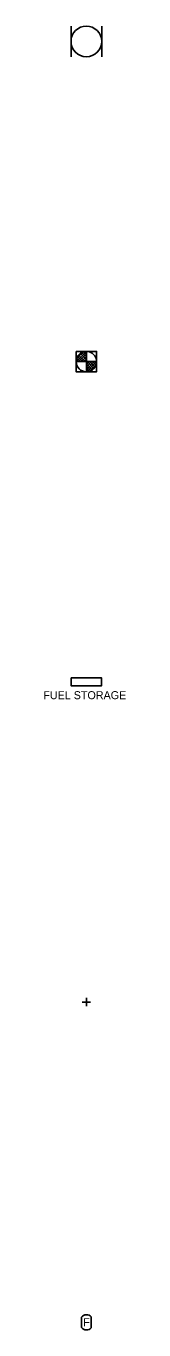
# Model space of a CAD drawing. Extents: x 98 to 2902, y -6 to 903.
# Drawn here: x 893.4 to 906.1, y -1.2 to 202.4 of the extents above; entities that cross this region are included whole.
import ezdxf

# ---------------------------------------------------------------- set-up
doc = ezdxf.new("R2010")
doc.units = 0
for name, color, linetype in [('V-FUEL-DEVC', 7, 'Continuous'), ('V-FUEL-TANK', 7, 'Continuous'), ('V-FUEL-VALT', 7, 'Continuous'), ('V-SITE-OTLN', 7, 'Continuous')]:
    doc.layers.add(name, color=color, linetype=linetype)

msp = doc.modelspace()

# ---------------------------------------------------------------- linework, layer by layer
at = {"layer": 'V-FUEL-DEVC'}
for p, q in [((897.61, 202.39), (897.61, 197.61)), ((902.39, 202.39), (902.39, 197.61)), ((900, 50), (899.35, 50)), ((900, 50.65), (900, 49.35)), ((900, 50), (900.65, 50))]:
    msp.add_line(p, q, dxfattribs=at)
msp.add_circle((900, 200), 2.39, dxfattribs=at)
at = {"layer": 'V-FUEL-TANK'}
msp.add_lwpolyline([(897.62, 100.6), (897.62, 99.4), (902.38, 99.4), (902.38, 100.6)], close=True, dxfattribs=at)
at = {"layer": 'V-FUEL-VALT'}
for points in [[(899.23, 0.81), (899.23, -0.81)], [(900.77, -0.85), (900.77, 0.85)]]:
    msp.add_lwpolyline(points, dxfattribs=at)
for centre, start, end in [((900.02, 0.19), 41.5928, 141.618), ((900.02, -0.19), 218.382, 318.4072)]:
    msp.add_arc(centre, 1, start, end, dxfattribs=at)
at = {"layer": 'V-SITE-OTLN'}
for p, q in [((900, 151.59), (898.41, 150)), ((899.53, 151.51), (898.49, 150.47)), ((898.64, 150.81), (899.45, 150)), ((900, 151.24), (898.76, 150)), ((898.8, 151.03), (899.83, 150.02)), ((899.07, 151.27), (900, 150.32)), ((900, 150.81), (899.19, 150)), ((899.3, 151.42), (900, 150.72)), ((899.57, 151.53), (900, 151.1)), ((900, 148.41), (900, 151.59)), ((898.41, 150), (901.59, 150)), ((898.43, 150.19), (898.61, 150)), ((898.51, 150.53), (899.04, 150)), ((900, 150.38), (899.62, 150)), ((900, 148.41), (901.59, 150)), ((900, 149.62), (900.38, 150)), ((900, 148.78), (901.22, 150)), ((900, 149.21), (900.79, 150)), ((900.91, 148.73), (900, 149.66)), ((900.68, 148.57), (900, 149.27)), ((900.4, 148.47), (900, 148.89)), ((901.19, 148.95), (900.14, 150)), ((900.47, 148.49), (901.51, 149.53)), ((901.34, 149.18), (900.53, 150)), ((901.48, 149.47), (900.95, 150)), ((901.57, 149.79), (901.36, 150))]:
    msp.add_line(p, q, dxfattribs=at)
msp.add_lwpolyline([(898.41, 151.59), (898.41, 148.41), (901.59, 148.41), (901.59, 151.59)], close=True, dxfattribs=at)
msp.add_circle((900, 150), 1.59, dxfattribs=at)

# ---------------------------------------------------------------- texts
at = {"layer": 'V-FUEL-TANK'}
msp.add_text('FUEL STORAGE', height=1.25, dxfattribs=at).set_placement((893.3, 97.29))
at = {"layer": 'V-FUEL-VALT'}
msp.add_text('F', height=1.25, dxfattribs=at).set_placement((899.51, -0.62))

doc.saveas('drawing.dxf')
